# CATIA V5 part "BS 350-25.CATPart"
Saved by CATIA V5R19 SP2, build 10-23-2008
Part number: BS 300-25
Bounding box of the stored display mesh (mm): x -15.868 to 15.868, y -15.868 to 15.868, z 0 to 80
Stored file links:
  C:\Users\Bora\Desktop\3D Katı model\BS serisi\BS 300\BS 300-25.CATPart
  C:\Program Files\Dassault Systemes\B19\intel_a\reffiles\standard\MetricThickPitch.txt
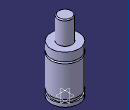
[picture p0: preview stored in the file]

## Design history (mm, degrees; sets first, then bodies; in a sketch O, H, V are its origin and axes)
Body1 (main body)
  Sketch1 on yz-plane, origin (0, 0, 0), H (0, 1, 0), V (0, 0, 1)
    point P1 (8, 79)
    point P3 (8, 79)
    point P5 (16, 44.5)
    point P6 (16, 42.5)
    point P9 (16, 44.5)
    point P14 (16, 42.5)
    line L1 (8, 79) -> (8, 54)
    arc A1 centre (7, 79) radius 1 from (8, 79) to (7, 80) ccw
    arc A2 centre (16, 43.5) radius 1 from (16, 44.5) to (16, 42.5) ccw
    line L2 (16, 0) -> (16, 4)
    line L3 (16, 44.5) -> (16, 54)
    line L4 (14.5, 7.5) -> (14.5, 4)
    line L5 (16, 7.5) -> (16, 42.5)
    line L6 (7, 80) -> (0, 80)
    point P15 (0, 80)
    line L7 (8, 54) -> (16, 54)
    line L8 (0, 0) -> (16, 0)
    line L9 (14.5, 7.5) -> (16, 7.5)
    line L10 (14.5, 4) -> (16, 4)
    coincidence: P15 V, P1 P3, P5 P9, P6 P14
    tangency: L6 A1
    horizontal: L7 H, L8 H, L9 H, L10 H
  Shaft1: profile Sketch1, axis Sketch1.V, angle 360
  Sketch2 on face of Shaft1 from Sketch1.L8, origin (0, 0, 0), H (1, 0, 0), V (0, -1, 0)
    point P1 (0, 0)
  Hole1: placed by Sketch2, at (0, 0, 0) direction (0, 0, 1), diameter 6.647, depth 4, threaded "M8", thread diameter 8, thread depth 4, pitch 1.25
